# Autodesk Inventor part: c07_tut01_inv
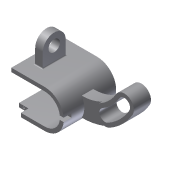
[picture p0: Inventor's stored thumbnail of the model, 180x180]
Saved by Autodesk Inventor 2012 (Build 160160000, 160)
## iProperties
Created: 2010-03
Part Number: c07_tut01_inv
Document SubType Name: Modeling
Designer: CADSoft
Density: 1 g/cm^3
Material: Default
Author: CADSoft
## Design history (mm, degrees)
sketch "Sketch1"
  geometry: 1 further point
sketch "Sketch2"
  geometry: L1 (0, 20)-(35, 20); L2 (35, 20)-(35, 16); L3 (35, 16)-(0, 16); L4 (0, -16)-(35, -16); L5 (35, -16)-(35, -20); L6 (35, -20)-(0, -20); A1 r 20 centre (0, 0) between (0, 20) and (0, -20); A2 r 16 centre (0, 0) between (0, 16) and (0, -16); 1 further point
  constraints: 12 end point, 4 point on circle, 3 equal length, 2 centre point, 1 coincident
  dimensions: "d0" = 20 radius of A1; "d1" = 35 distance of L1.start L1.end; "d2" = 4 distance of L1.end L2.end
extrude "Extrusion1" new body sketch "Sketch2" stored distance "d3" = 55; taper "d4" = 0 deg
sketch "Sketch3"
  geometry: A1 r 45 centre (-17.5, 55) between (-56.409, 32.393) and (-17.32, 10); A2 r 65 centre (-17.5, 55) between (-73.702, 22.345) and (-17.321, -10); A3 r 20 centre (0, 0) between (-17.32, 10) and (-17.321, -10); A4 r 10 centre (-65.055, 27.369) between (-56.409, 32.393) and (-73.702, 22.345); 1 further point
  constraints: 8 point on circle, 4 centre point, 2 coincident, 2 tangent
  dimensions: "d5" = 45 radius of A1; "d6" = 65 radius of A2; "d7" = 17.5 horizontal distance of point (0, 0) A1.centre; "d8" = 55 vertical distance of point (0, 0) A1.centre; "d9" = 60 deg dimension on A1.centre A2.start A2.end; "d10" = 20 radius of A3
extrude "Extrusion2" join sketch "Sketch3" stored distance "d11" = 12; taper "d12" = 0 deg
hole "Hole1" diameter "d52" = 2; stored, may be unused: countersink angle "d56" = 90 deg, drill point angle "d58" = 118 deg; dims "d50" = 5, "d51" = 2, "d53" = 6, "d54" = 4, "d55" = 2, "d57" = 4
body "Solid1"
sketch "Sketch4"
  geometry: A1 r 45 centre (-17.5, 55) between (-56.409, 32.393) and (-39.892, 15.967); A2 r 65 centre (-17.5, 55) between (-73.702, 22.345) and (-49.845, -1.381); A3 r 10 centre (-65.055, 27.369) between (-56.409, 32.393) and (-73.702, 22.345); A4 r 10 centre (-44.868, 7.293) between (-49.845, -1.381) and (-39.892, 15.967); A5 r 10 centre (-65.055, 27.369) between (-56.409, 32.393) and (-73.702, 22.345) reference; A6 r 45 centre (-17.5, 55) between (-56.409, 32.393) and (-17.32, 10) reference; A7 r 65 centre (-17.5, 55) between (-73.702, 22.345) and (-17.321, -10) reference; 1 further point
  constraints: 8 point on circle, 4 centre point, 4 tangent, 3 concentric, 1 coincident
  dimensions: "d30" = 10 radius of A3; "d31" = 30 deg dimension on A1.centre A4.centre A3.centre
extrude "Extrusion3" join sketch "Sketch4" stored distance "d32" = 18; taper "d33" = 0 deg
sketch "Sketch5"
  geometry: A1 r 10 centre (65.055, 27.369) between (73.702, 22.345) and (56.409, 32.393) reference; A2 r 45 centre (17.5, 55) between (39.892, 15.967) and (56.409, 32.393) reference; A3 r 10 centre (44.868, 7.293) between (39.892, 15.967) and (49.845, -1.381) reference; A4 r 65 centre (17.5, 55) between (49.845, -1.381) and (73.702, 22.345) reference; A5 r 6 centre (65.055, 27.369) between (70.243, 24.354) and (59.867, 30.383); A6 r 61 centre (17.5, 55) between (47.854, 2.088) and (70.243, 24.354); A7 r 6 centre (44.868, 7.293) between (41.883, 12.497) and (47.854, 2.088); A8 r 49 centre (17.5, 55) between (41.883, 12.497) and (59.867, 30.383); 1 further point
  constraints: 8 point on circle, 4 centre point, 3 other
  dimensions: "d34" = 6 radius of A5
extrude "Extrusion4" cut sketch "Sketch5" distance "d35" = 18; taper "d36" = 0 deg
workplane "Work Plane1"
sketch "Sketch10"
  geometry: L1 (4, 15.5)-(4, 39.5); L2 (4, 39.5)-(19, 39.5); L3 (19, 15.5)-(4, 15.5); L4 (4, 55)-(4, 0) reference; L5 (-36, 55)-(4, 55) reference; C1 r 6 at (19, 27.5); A1 r 12 centre (19, 27.5) between (19, 15.5) and (19, 39.5); 1 further point
  constraints: 6 end point, 2 centre point, 2 point on circle, 2 point on line, 1 coincident, 1 parallel, 1 perpendicular, 1 tangent
  dimensions: "d38" = 12 radius of A1; "d39" = 27.5 distance from line of L5 A1.centre; "d40" = 15 distance from line of L4 A1.centre; "d41" = 12 diameter of C1
extrude "Extrusion5" join sketch "Sketch10" distance "d42" = 8; taper "d43" = 0 deg
fillet "Fillet1" dims "d44" = 1
sketch "Sketch11"
  geometry: L1 (0, -20)-(-35, -20) reference; L2 (-35, -16)-(-25, -16); L3 (-25, -16)-(-25, -20); L4 (-25, -20)-(-35, -20); L5 (-35, -20)-(-35, -16); L6 (15.875, 2)-(19.9, 2); L7 (15.875, -2)-(19.9, -2); A1 r 20 centre (0, 0) between (0, -20) and (0, 20) reference; A2 r 16 centre (0, 0) between (0, -16) and (0, 16) reference; A3 r 16 centre (0, 0) between (15.875, -2) and (15.875, 2); A4 r 20 centre (0, 0) between (19.9, -2) and (19.9, 2)
  constraints: 12 end point, 8 point on circle, 2 centre point, 1 point on line
  dimensions: "d45" = 10 distance of L2.start L2.end; "d46" = 4 distance between parallel lines of L7 L6; "d47" = 2 distance from line of A1.centre L6
extrude "Extrusion6" cut sketch "Sketch11" distance "d48" = 8; taper "d49" = 0 deg
other parameters: "d37" = -17.5
